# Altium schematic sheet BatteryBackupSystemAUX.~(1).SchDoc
size 431 x 279 mm; Date: Not shown in title block; ApprovedBy: Not shown in title block; CheckedBy: Not shown in title block; Author: Not shown in title block; CompanyName: Not shown in title block; Engineer: Not shown in title block; Organization: Not shown in title block; Address1: Not shown in title block; Address2: Not shown in title block; Address3: Not shown in title block; Address4: Not shown in title block; DocumentNumber: 1; Revision: Use project parameter SCH_Rev; SheetNumber: 4; SheetTotal: 4; PageSetup: Record=PageOptions¦CenterHorizontal=True¦CenterVertical=True¦PrintScale=1.00¦XCorrection=1.00¦YCorrection=1.00¦PrintKind=0¦BorderSize=5000000¦LeftOffset=0¦BottomOffset=0¦Orientation=2¦PaperLength=1000¦PaperWidth=1000¦Scale=100¦PaperSource=15¦PrintQuality=600¦MediaType=1¦DitherType=10¦PaperKind=Letter¦PrintScaleMode=1
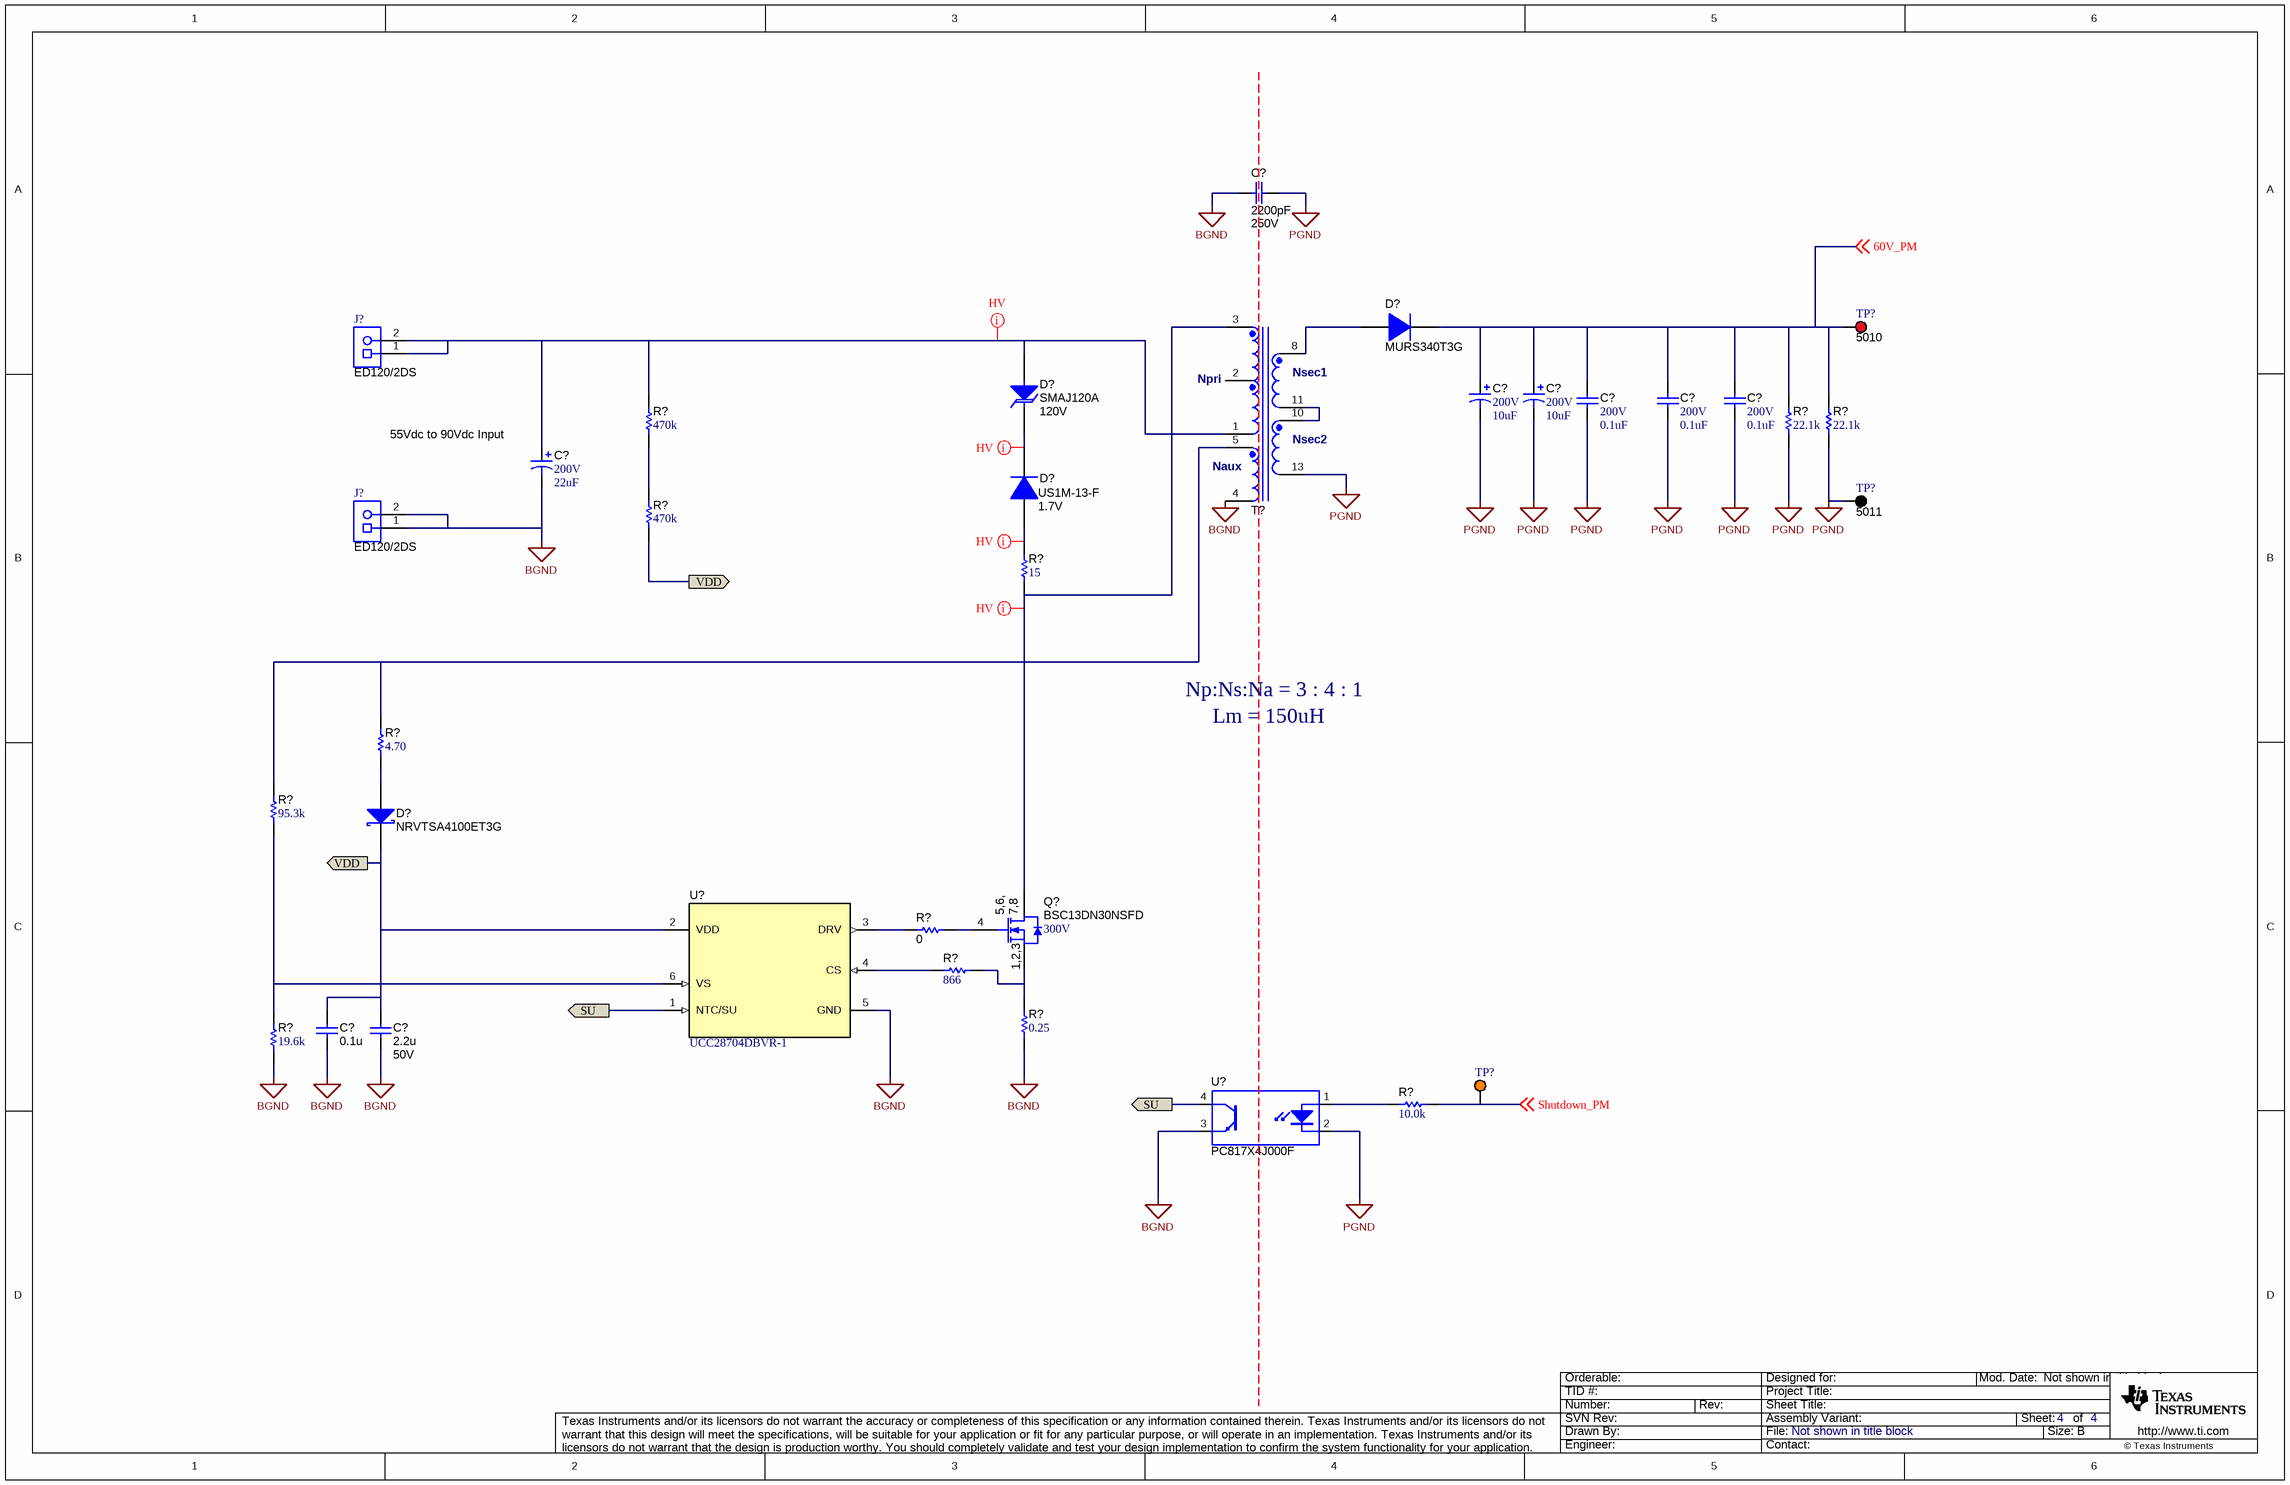
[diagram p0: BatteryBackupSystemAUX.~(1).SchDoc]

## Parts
(Parts that share a designator on the sheet are numbered #1, #2 ... from top to bottom, then left to right.)
C?#1  ValueDisplayed: 2200pF  Value2: 250V  [CAPRD750W60D1050H1450]  (hidden comment: CS11-E2GA222MYNS)
C?#2  VDC_V: 200V  ValueDisplayed: 10uF  [VK_800X1150]  (hidden comment: UVK2D100MPD)
C?#3  VDC_V: 200V  ValueDisplayed: 10uF  [VK_800X1150]  (hidden comment: UVK2D100MPD)
C?#4  VDC_V: 200V  ValueDisplayed: 0.1uF  [1206]  (hidden comment: C1206C104K2RACTU)
C?#5  VDC_V: 200V  ValueDisplayed: 0.1uF  [1206]  (hidden comment: C1206C104K2RACTU)
C?#6  VDC_V: 200V  ValueDisplayed: 0.1uF  [1206]  (hidden comment: C1206C104K2RACTU)
C?#7  VDC_V: 200V  ValueDisplayed: 22uF  [UPW_1000x2000]  (hidden comment: UPW2D220MPD1TD)
C?#8  ValueDisplayed: 0.1u  [0603]  (hidden comment: 06035C104KAT2A)
C?#9  ValueDisplayed: 2.2u  Value2: 50V  [1206]  (hidden comment: GRM31CR61H225KA88L)
D?#1  MURS340T3G  [SMC]
D?#2  SMAJ120A  value 120V  [SMA]
D?#3  US1M-13-F  value 1.7V  [SMA]
D?#4  NRVTSA4100ET3G  [SMA]
J?#1  ED120/2DS  [On-Shore_ED120_2DS]
J?#2  ED120/2DS  [On-Shore_ED120_2DS]
Q?  BSC13DN30NSFD  value 300V  [PG-TDSON-8]
R?#1  ValueDisplayed: 470k  [1206]  (hidden comment: RC1206FR-07470KL)
R?#2  ValueDisplayed: 22.1k  [1206]  (hidden comment: RC1206FR-0722K1L)
R?#3  ValueDisplayed: 22.1k  [1206]  (hidden comment: RC1206FR-0722K1L)
R?#4  ValueDisplayed: 470k  [1206]  (hidden comment: RC1206FR-07470KL)
R?#5  ValueDisplayed: 15  [1206]  (hidden comment: CRCW120615R0JNEA)
R?#6  ValueDisplayed: 4.70  [1206]  (hidden comment: RC1206FR-074R7L)
R?#7  ValueDisplayed: 95.3k  [0603]  (hidden comment: RC0603FR-0795K3L)
R?#8  value 0  [0603]  (hidden comment: CRCW06030000Z0EA)
R?#9  ValueDisplayed: 866  [0603]  (hidden comment: RC0603FR-07866RL)
R?#10  ValueDisplayed: 0.25  [1206]  (hidden comment: CSR1206FKR250)
R?#11  ValueDisplayed: 19.6k  [0603]  (hidden comment: RC0603FR-0719K6L)
R?#12  ValueDisplayed: 10.0k  [0603]  (hidden comment: M55342K12B10E0T)
T?  750314727  [WURTH_750314727]  (value not drawn)
TP?#1  5010  [Keystone5010]
TP?#2  5011  [Keystone5011]
TP?#3  5013  [Keystone5013]  (value not drawn)
U?#1  UCC28704DBVR-1  [DBV0006A_N]
U?#2  PC817X4J000F  [DIP762W60P254L460H350Q4B]

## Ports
SU (out), VDD (out)

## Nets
BGND: C?#1.2 C?#7.2(-) C?#8.2 C?#9.2 J?#2.1 J?#2.2 R?#10.1 R?#11.1 T?.4 U?#1.5(GND) U?#2.3(E)
PGND: C?#1.1 C?#2.2(-) C?#3.2(-) C?#4.2 C?#5.2 C?#6.2 R?#2.1 R?#3.1 T?.13 TP?#2.1 U?#2.2(K)
60V_PM: C?#2.1(+) C?#3.1(+) C?#4.1 C?#5.1 C?#6.1 D?#1.1(K) R?#2.2 R?#3.2 TP?#1.1 ; off-sheet 60V_PM
Shutdown_PM: R?#12.2 TP?#3.1 ; off-sheet Shutdown_PM
SU: U?#1.1(NTC/SU) U?#2.4(C) ; port SU
VDD: C?#8.1 C?#9.1 D?#4.1(K) R?#4.1 U?#1.2(VDD) ; port VDD
NetC?#7_1: C?#7.1(+) D?#2.2(A) J?#1.1 J?#1.2 R?#1.2 T?.1
NetD?#1_2: D?#1.2(A) T?.8
NetD?#2_1: D?#2.1(K) D?#3.1(K)
NetD?#3_2: D?#3.2(A) R?#5.2
NetD?#4_2: D?#4.2(A) R?#6.1
NetQ?_1: Q?.1(S) Q?.2(S) Q?.3(S) R?#9.2 R?#10.2
NetQ?_4: Q?.4(G) R?#8.2
NetQ?_5: Q?.5(D) Q?.6(D) Q?.7(D) Q?.8(D) Q?.9(D) R?#5.1 T?.3
NetR?#1_1: R?#1.1 R?#4.2
NetR?#6_2: R?#6.2 R?#7.2 T?.5
NetR?#7_1: R?#7.1 R?#11.2 U?#1.6(VS)
NetR?#8_1: R?#8.1 U?#1.3(DRV)
NetR?#9_1: R?#9.1 U?#1.4(CS)
NetR?#12_1: R?#12.1 U?#2.1(A)
NetT?_10: T?.10 T?.11

Not connected (* = marked no-connect by the designer): T? 2

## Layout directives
net class HV: NetC?#7_1, NetD?#2_1, NetD?#3_2, NetQ?_5

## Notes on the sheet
- (near C?#7) 55Vdc to 90Vdc Input
- (near T?) Npri
- (near T?) Nsec1
- (near T?) Naux
- (near T?) Nsec2
- Np:Ns:Na = 3 : 4 : 1
- Lm = 150uH

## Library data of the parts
C?#1 = CS11-E2GA222MYNS: CAP, CERM, 2200pF, 250V, +/-20%, E, Radial Disc D10.5x7mm; Manufacturer: TDK; Polarized: N; CompType: Capacitor; U/M: EA; Cap_F: 0.0000000022; Tolerance_%: 20; Value1: Unknown; VDC_V: 250; TaMin_C: -25; TaMax_C: 105; Cap_Case: Disc, 10.5x7mm
C?#2 C?#3 = CMP-0064891-1: CAP, AL, 10 uF, 200 V, +/- 20%, TH; Manufacturer: Nichicon; TaMin_C: -40°C; Polarized: Y; SizeAreaWB_mm2: 100; Value1: Unknown; U/M: EA; Value: 10uF; TaMax_C: 85°C; SizeZ_mm: 13; SizeX_mm: 8; Cap_Case: 8x11.5mm; SizeArea_mm2: 64; CompType: Capacitor; AEC Qualified: N; Cap_F: 10µF; IRMS_A: 80mA; AEC Category: Q200
C?#4-C?#6 = CMP-0008585-2: CAP, CERM, 0.1 uF, 200 V, +/- 10%, X7R, 1206; Manufacturer: Kemet; TaMin_C: -55°C; Polarized: N; SizeAreaWB_mm2: 10.92; Value1: Unknown; U/M: EA; Value: 0.1uF; TaMax_C: 125°C; SizeZ_mm: 1.35; SizeX_mm: 3.2; SizeY_mm: 1.6; SizeArea_mm2: 5.12; Cap_F: 100nF; AEC Category: Q200
C?#7 = CMP-0064890-1: CAP, AL, 22 uF, 200 V, +/- 20%, TH; Manufacturer: Nichicon; TaMin_C: -40°C; Polarized: Y; SizeAreaWB_mm2: 144; Value1: Unknown; U/M: EA; Value: 22uF; TaMax_C: 105°C; SizeZ_mm: 22; SizeX_mm: 10; Cap_Case: 10x20mm; SizeArea_mm2: 100; CompType: Capacitor; AEC Qualified: N; Cap_F: 22µF; IRMS_A: 1.4dA; AEC Category: Q200
C?#8 = 06035C104KAT2A: CAP, CERM, 0.1uF, 50V, +/-10%, X7R, 0603; Manufacturer: AVX; Polarized: N; CompType: Capacitor; U/M: EA; Cap_F: 0.0000001; Tolerance_%: 10; Value1: Unknown; VDC_V: 50; TaMin_C: -55; TaMax_C: 125
C?#9 = GRM31CR61H225KA88L: CAP, CERM, 2.2uF, 50V, +/-10%, X5R, 1206; Manufacturer: MuRata; Polarized: N; CompType: Capacitor; U/M: EA; Cap_F: 0.0000022; Tolerance_%: 10; Value1: Unknown; VDC_V: 50; TaMin_C: -55; TaMax_C: 85
D?#1 = CMP-0076962-2: Diode, Ultrafast, 400 V, 3 A, SMC; Manufacturer: ON Semiconductor; AEC Category: Q101; Io_A: 3A; RJC_CperW: 11.0; SizeArea_mm2: 50.5686; SizeX_mm: 8.13; SizeZ_mm: 2.6; SizeAreaWB_mm2: 83.2686; TJmax_C: 175°C; Green_REACh: Incomplete; Value2: 1.25V; Vr_V: 400V; Green_Lifecycle: Not Set; SizeY_mm: 6.22; Value: 400V
D?#2 = SMAJ120A: Diode, TVS, Uni, 120V, 400W, SMA; Manufacturer: Littelfuse; U/M: EA; Power_W: 400; Vr_V: 120
D?#3 = US1M-13-F: Diode, Ultrafast, 1000V, 1A, SMA; Manufacturer: Diodes Inc.; U/M: EA; Vf_V: 1.7; Io_A: 1; Vr_V: 1000; TJmax_C: 150; RJC_CperW: 30
D?#4 = CMP-0081057-2: Diode, Schottky, 100 V, 4 A, AEC-Q101, SMA; Manufacturer: ON Semiconductor; SizeZ_mm: 2.87; SizeY_mm: 2.92; SizeAreaWB_mm2: 37.3428; Io_A: 4A; AEC Category: Q101; SizeX_mm: 5.59; Value: 100V; SizeArea_mm2: 16.3228; Value2: 0.68V; TJmax_C: 175°C; AEC Qualified: Y; Vf_V: 680mV
J?#1 J?#2 = CMP-0074910-1: Terminal Block, 5.08 mm, 2x1, Brass, TH; Manufacturer: On-Shore Technology; Cert_VDE: Y; CNHeader: False; Current_A: 15A; Green_Lifecycle: Not Set; Shrouded: N; Gender: Female; Green_REACh: Incomplete; Voltage_V: 300V; Row_Count: 1; Pitch_mm: 5.08; CT: True
Q? = CMP-0000907-1: MOSFET, N-CH, 300 V, 16 A, PG-TDSON-8; Alternate Manufacturer: None; Manufacturer: Infineon Technologies; SizeZ_mm: 1.12; ChType: N; SizeX_mm: 5.99; SizeY_mm: 4.9; Vgs_V: 20V; SizeArea_mm2: 29.351; IdsMax_A: 16A; SizeAreaWB_mm2: 55.131; U/M: EA; QgTyp_nC: 23
R?#1 R?#4 = CMP-0018313-2: RES, 470 k, 1%, 0.25 W, 1206; Manufacturer: Yageo America; Power_W: 250mW; TempCo: 100 ppm/C; U/M: EA; Value: 470k; SizeX_mm: 3.2; SizeY_mm: 1.6; SizeZ_mm: 1.35; Value2: 0.25W; SizeArea_mm2: 5.12; VDC_V: 200V; AEC Category: Q200
R?#2 R?#3 = CMP-0018082-2: RES, 22.1 k, 1%, 0.25 W, 1206; Manufacturer: Yageo America; Power_W: 250mW; TempCo: 100 ppm/C; Value_Code: 22k1; U/M: EA; Value: 22.1k; EIA_Code: E96; SizeX_mm: 3.2; SizeY_mm: 1.6; SizeZ_mm: 1.35; Value2: 0.25W; SizeArea_mm2: 5.12; VDC_V: 200V; AEC Category: Q200
R?#5 = CMP-0018594-3: RES, 15, 5%, 0.25 W, AEC-Q200 Grade 0, 1206; Manufacturer: Vishay-Dale; Power_W: 250mW; TempCo: 200 ppm/C; Value_Code: 15R0; Value: 15; EIA_Code: E24; SizeX_mm: 3.2; SizeY_mm: 1.6; SizeZ_mm: 1.35; Value2: 0.25W; SizeArea_mm2: 5.12; AEC Qualified: Y; VDC_V: 200V; AEC Category: Q200; AEC Grade: 0
R?#6 = CMP-0018350-2: RES, 4.70, 1%, 0.25 W, 1206; Manufacturer: Yageo America; Power_W: 250mW; TempCo: 200 ppm/C; Value_Code: 4R70; U/M: EA; Value: 4.70; Res_ohm: 4.7; SizeX_mm: 3.2; SizeY_mm: 1.6; SizeZ_mm: 1.35; Value2: 0.25W; SizeArea_mm2: 5.12; VDC_V: 200V; AEC Category: Q200
R?#7 = CMP-0023326-5: RES, 95.3 k, 1%, 0.1 W, 0603; Manufacturer: Yageo; Power_W: 100mW; TempCo: 100 ppm/C; Value_Code: 95k3; Value: 95.3k; EIA_Code: E96; SizeX_mm: 1.6; SizeY_mm: 0.8; SizeZ_mm: 1; Value2: 0.1W; SizeArea_mm2: 1.28; AEC Qualified: N; VDC_V: 75V; AEC Category: Q200; SizeAreaWB_mm2: 4.68
R?#8 = CRCW06030000Z0EA: RES, 0 ohm, 5%, 0.1W, 0603; Manufacturer: Vishay-Dale; CompType: Resistor; Value_Code: 0000; Tolerance_%: 5; Power_W: 0.1; VDC_V: 75; TempCo: 200 ppm/C; EIA_Code: E24; U/M: EA
R?#9 = CMP-0023300-5: RES, 866, 1%, 0.1 W, 0603; Manufacturer: Yageo; Power_W: 100mW; TempCo: 100 ppm/C; Value_Code: 866R; Value: 866; EIA_Code: E96; SizeX_mm: 1.6; SizeY_mm: 0.8; SizeZ_mm: 1; Value2: 0.1W; SizeArea_mm2: 1.28; AEC Qualified: N; VDC_V: 75V; AEC Category: Q200; SizeAreaWB_mm2: 4.68
R?#10 = CMP-0017267-2: RES, 0.25, 1%, 0.5 W, 1206; Manufacturer: Stackpole Electronics Inc; Power_W: 500mW; TempCo: 100 ppm/C; Value_Code: R250; U/M: EA; Value: 0.25; Res_ohm: 2.5d; SizeX_mm: 3.2; SizeY_mm: 1.6; SizeZ_mm: 1.35; Value2: 0.5W; SizeArea_mm2: 5.12; AEC Category: Q200
R?#11 = CMP-0022861-5: RES, 19.6 k, 1%, 0.1 W, 0603; Manufacturer: Yageo; Power_W: 100mW; TempCo: 100 ppm/C; Value_Code: 19k6; Value: 19.6k; EIA_Code: E96; SizeX_mm: 1.6; SizeY_mm: 0.8; SizeZ_mm: 1; Value2: 0.1W; SizeArea_mm2: 1.28; AEC Qualified: N; VDC_V: 75V; AEC Category: Q200; SizeAreaWB_mm2: 4.68
R?#12 = CMP-0080488-1: RES, 10.0 k, 1%, 0.1 W, 0603; Manufacturer: TT Electronics/IRC; Power_W: 100mW; TempCo: 100 ppm/C; SizeAreaWB_mm2: 4.68; Value_Code: 10k0; Value: 10.0k; EIA_Code: E96; Res_ohm: 10k; SizeX_mm: 1.6; SizeY_mm: 0.8; SizeZ_mm: 1; Value2: 0.1W; SizeArea_mm2: 1.28; AEC Qualified: N; AEC Category: Q200
T? = 750314727: Transformer, 80uH, TH; Manufacturer: Wurth Elektronik eiSos; SymbolCreator: x0208325; DCR_Ohm: 0.221; Value: 250uH; LeakageL: TBD; U/M: EA
TP?#1 = CMP-0055147-2: Test Point, Multipurpose, Red, TH; Manufacturer: Keystone Electronics; CT: TRUE; ContactFinish: Silver; Green_Lifecycle: Active; CNHeader: FALSE; Green_REACh: Passed
TP?#2 = CMP-0055148-2: Test Point, Multipurpose, Black, TH; Manufacturer: Keystone Electronics; CNHeader: FALSE; ContactFinish: Silver; Green_REACh: Passed; Green_Lifecycle: Active; CT: TRUE
TP?#3 = CMP-0055150-2: Test Point, Multipurpose, Orange, TH; Manufacturer: Keystone Electronics; CT: TRUE; ContactFinish: Silver; Green_REACh: Passed; CNHeader: FALSE; Green_Lifecycle: Active
U?#1 = CMP-0074087-1: Off-Line Constant-Voltage Constant-Current Flyback Controller With Primary-Side Regulation (PSR), DBV0006A (SOT-23-6); Alternate PartNumber: UCC28704DBVT-1; Alternate Manufacturer: Texas Instruments; Green_Lifecycle: Active; SizeAreaWB_mm2: 14.82; Green_REACh: Passed; U/M: EA; SizeZ_mm: 1.45; SizeX_mm: 2.8; SizeY_mm: 2.9; SizeArea_mm2: 8.12; CompType: IC
U?#2 = LTV-817: Opto-Isolator, 1 Channel, TH; CompType: OPTOCOUPLER; U/M: EA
